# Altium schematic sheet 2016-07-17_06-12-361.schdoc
size 262 x 111 mm; SheetNumber: 1; SheetTotal: 1
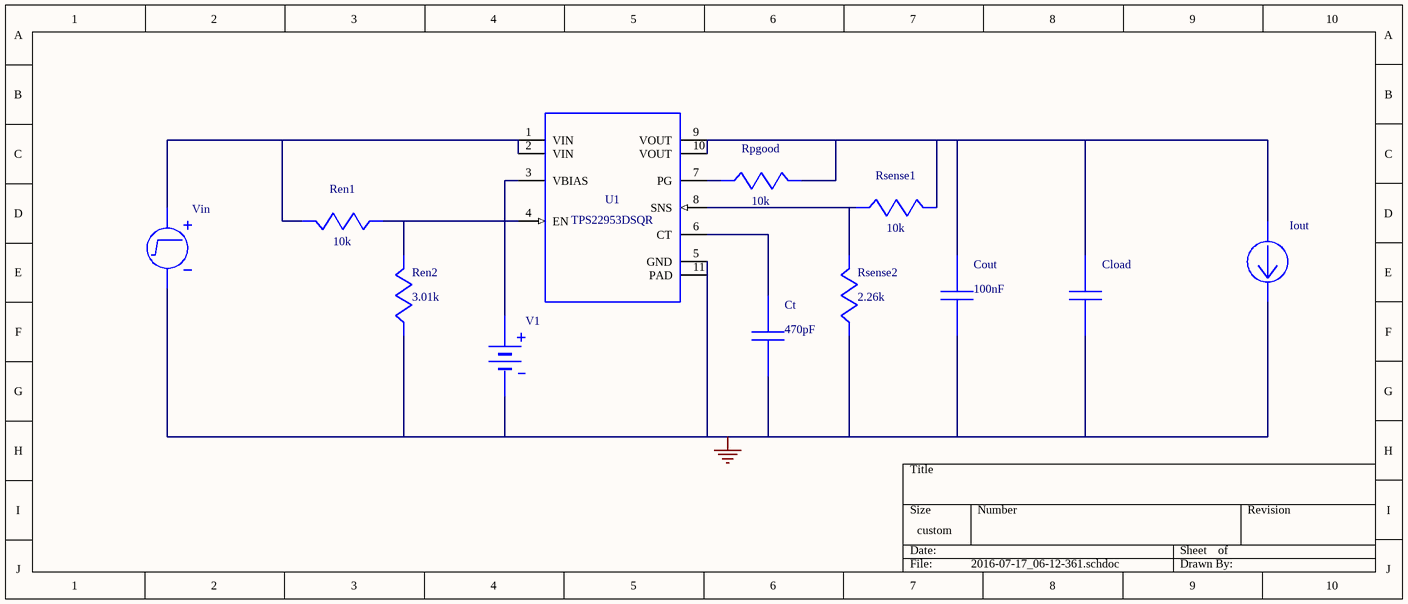
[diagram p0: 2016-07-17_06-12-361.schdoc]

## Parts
Cload  GRM21BR71E104KA01L  (value not drawn)
Cout  value 100nF  (hidden comment: GRM155R60J104KA01D)
Ct  value 470pF  (hidden comment: CC0805KRX7R9BB471)
Iout  WB_CURRENT_LOAD  (value not drawn)
Ren1  value 10k  (hidden comment: CRCW040210K0FKED)
Ren2  value 3.01k  (hidden comment: CRCW04023K01FKED)
Rpgood  value 10k  (hidden comment: CRCW040210K0FKED)
Rsense1  value 10k  (hidden comment: CRCW040210K0FKED)
Rsense2  value 2.26k  (hidden comment: CRCW04022K26FKED)
U1  TPS22953DSQR
V1  WB_PRIMITIVE_BATTERY  (value not drawn)
Vin  WB_STARTUP_VOLTAGE_SOURCE  (value not drawn)

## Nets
0: Cload.2 Cout.2 Ct.2 Iout.2(-) Ren2.2 Rsense2.2 U1.5(GND) U1.11(PAD) V1.2(-) Vin.2(-)
NetCload_1: Cload.1 Cout.1 Iout.1(+) Rpgood.1 Rsense1.1 U1.9(VOUT) U1.10(VOUT)
NetCt_1: Ct.1 U1.6(CT)
NetRen1_1: Ren1.1 U1.1(VIN) U1.2(VIN) Vin.1(+)
NetRen1_2: Ren1.2 Ren2.1 U1.4(EN)
NetRpgood_2: Rpgood.2 U1.7(PG)
NetRsense1_2: Rsense1.2 Rsense2.1 U1.8(SNS)
NetU1_3: U1.3(VBIAS) V1.1(+)

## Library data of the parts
Cload = GRM21BR71E104KA01L: WB_PRIMITIVE_CAP; Manufacturer Name: WB_PRIMITIVE_CAPACITOR
Cout = GRM155R60J104KA01D: GRM155R60J104KA0; Manufacturer Name: MuRata
Ct = CC0805KRX7R9BB471: CC0805KRX7R9BB47; Manufacturer Name: Yageo America
Ren1 Rpgood Rsense1 = CRCW040210K0FKED: Manufacturer Name: Vishay-Dale
Ren2 = CRCW04023K01FKED: Manufacturer Name: Vishay-Dale
Rsense2 = CRCW04022K26FKED: Manufacturer Name: Vishay-Dale
U1 = TPS22953DSQR: Manufacturer Name: Texas Instruments
V1 = WB_PRIMITIVE_BATTERY: WB_PRIMITIVE_BAT
Vin = WB_STARTUP_VOLTAGE_SOURCE: WB_STARTUP_VOLTA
